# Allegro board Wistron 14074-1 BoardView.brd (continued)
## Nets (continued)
HDMI2_CLK_CON_P: C15163.2 ED2305.4 ED2305.7 EL5608.1 EL5608.2 HDMI2.10 R5610.1 R9696.1
HDMI2_CLK_CPU_N: C15164.1 CPU1.F44
HDMI2_CLK_CPU_P: C15163.1 CPU1.D44
HDMI2_DATA_CON_N0: C15166.2 ED2305.2 ED2305.9 EL5607.3 EL5607.4 HDMI2.9 R5609.2 R9691.1
HDMI2_DATA_CON_N1: C15170.2 ED2306.5 ED2306.6 EL5606.3 EL5606.4 HDMI2.6 R5608.2 R9694.1
HDMI2_DATA_CON_N2: C15172.2 ED2306.2 ED2306.9 EL5605.3 EL5605.4 HDMI2.3 R5607.2 R9697.1
HDMI2_DATA_CON_P0: C15165.2 ED2305.1 ED2305.10 EL5607.1 EL5607.2 HDMI2.7 R5609.1 R9692.1
HDMI2_DATA_CON_P1: C15167.2 ED2306.4 ED2306.7 EL5606.1 EL5606.2 HDMI2.4 R5608.1 R9693.1
HDMI2_DATA_CON_P2: C15171.2 ED2306.1 ED2306.10 EL5605.1 EL5605.2 HDMI2.1 R5607.1 R9695.1
HDMI2_DATA_CPU_N0: C15166.1 CPU1.G42
HDMI2_DATA_CPU_N1: C15170.1 CPU1.K40
HDMI2_DATA_CPU_N2: C15172.1 CPU1.G40
HDMI2_DATA_CPU_P0: C15165.1 CPU1.F42
HDMI2_DATA_CPU_P1: C15167.1 CPU1.J40
HDMI2_DATA_CPU_P2: C15171.1 CPU1.F40
HDMI2_DDCCLK_CON: EC7613.1 ED2304.3 HDMI2.15 Q6517.D R9689.2
HDMI2_DDCCLK_CPU: CPU1.T51 Q6517.S RN5402.1(A)
HDMI2_DDCCLK_G: Q6517.G RN5603.1(A) RN5603.2(A)
HDMI2_DDCDATA_CON: EC7612.1 ED2304.4 HDMI2.16 Q6518.D R9690.2
HDMI2_DDCDATA_CPU: CPU1.T52 Q6518.S RN5402.2(A)
HDMI2_DDCDATA_G: Q6518.G RN5604.1(A) RN5604.2(A)
HDMI2_HPD_CON: ED2304.1 HDMI2.19 Q6503.G R6542.1 R6557.1
HDMI2_HPD_CPU#: CPU1.U51 Q6503.D R6535.1 R6557.2
HDMI2_LS_R: Q6519.D R9691.2 R9692.2 R9693.2 R9694.2 R9695.2 R9696.2 R9697.2 R9698.2
HUB_AVDD: C4606.1 C4607.1 C4608.1 C4609.1 C4610.1 L5305.2 U4601.5 U4601.9 U4601.14
HUB_DVDD: C4601.2 C4605.1 C4611.1 L5305.1 R4602.1 R4604.1 R4608.2 R4609.1 TC4601.1 U4601.21 U4601.28 U4602.8
HUB_OC14_L: R4611.2 R4612.1 U4601.19 U4601.25
HUB_OC23_L: R4613.2 R4614.1 U4601.20 U4601.24
HUB_PGANG: R4607.1 U4601.23
HUB_PSELF: R4604.2 R4605.1 U4601.22
HUB_RESET#: C4602.1 R4602.2 R4603.1 U4601.17
HUB_RREF: R4606.1 U4601.8
HUB_SDA: R4608.1 U4601.26 U4602.5
HUB_TEST/SCL: U4601.18 U4602.6
HUB_X1: C4603.2 U4601.10 X3501.3
HUB_X2: C4604.2 U4601.11 X3501.1
HWM_REF: C2008.1 R2018.2 R2019.2 SIO1.47
ICLKICOMP: CPU1.P20 R1534.2
ICLKRCOMP: CPU1.N20 R1535.2
INT_SERIRQ_CPU: CPU1.T2 R9671.1 U2402.3
INT_SERIRQ_OE: R2474.2 R2475.1 U2402.5
JDREF: AUDIO1.40 R2213.1
KA20GATE: R2030.2 SIO1.21
KBCLK: RN5410.3(A) SIO1.39
KBDATA: RN5410.4(A) SIO1.38
KBRST_N: C2018.2 R2029.2 SIO1.20
LAD0_FWH0: CPU1.M3 DBGH1.9 SIO1.16
LAD1_FWH1: CPU1.M2 DBGH1.7 SIO1.17
LAD2_FWH2: CPU1.N3 DBGH1.3 SIO1.18
LAD3_FWH3: CPU1.N1 DBGH1.1 SIO1.19
LAN_CLKREQ_CPU#: CPU1.AM14 D2101.A R2110.1 R6519.1 R9852.1
LAN_CLKREQB: D2101.K LAN1.12 R2110.2 R2112.1
LAN_CONN_CVT: C2813.1 U3RJ1.R1
LAN_ISOLATEB: LAN1.20 R2108.1 R2109.1
LAN_LED*: L3401.2 R3422.2
LAN_LED*_EMI: L3401.1 LEDH1.12
LAN_LED_ACT: C2811.1 R2811.1 U3RJ1.L14
LAN_LED_ACT_C: LAN1.27 R2105.1
LAN_LED_ACTIVE: ED3203.1 R2105.2 R6401.2 U3RJ1.L13
LAN_LEDC0: Q3401.C R3422.1
LAN_LEDC1: Q3401.B R3420.1
LAN_LEDC1_E: Q6550.D R3418.2 R3420.2
LAN_LEDC1_E1: Q6550.S R3419.2 R6401.1 R6402.1 R6403.1
LAN_LINK_100: ED3203.3 LAN1.26 R2813.2
LAN_LINK_100_R: C2810.1 R2810.1 R2813.1 U3RJ1.L12
LAN_LINK_1000: ED3203.4 LAN1.25 R2814.2
LAN_LINK_1000_R: C2809.1 R2801.1 R2814.1 U3RJ1.L11
LAN_MDI0_DN: EC2802.1 ED2804.4 EL5337.1 EL5337.2 LAN1.2 U3RJ1.R3
LAN_MDI0_DP: EC2804.1 ED2804.3 EL5337.3 EL5337.4 LAN1.1 U3RJ1.R2
LAN_MDI1_DN: EC2806.1 ED2804.1 EL5316.1 EL5316.2 LAN1.5 U3RJ1.R5
LAN_MDI1_DP: EC2807.1 ED2804.6 EL5316.3 EL5316.4 LAN1.4 U3RJ1.R4
LAN_MDI2_DN: EC2803.1 ED2802.4 EL5317.1 EL5317.2 LAN1.7 U3RJ1.R7
LAN_MDI2_DP: EC2805.1 ED2802.3 EL5317.3 EL5317.4 LAN1.6 U3RJ1.R6
LAN_MDI3_DN: EC2801.1 ED2802.1 EL5318.1 EL5318.2 LAN1.10 U3RJ1.R9
LAN_MDI3_DP: EC2808.1 ED2802.6 EL5318.3 EL5318.4 LAN1.9 U3RJ1.R8
LAN_RSET: LAN1.31 R2106.2
LAN_WAKEB: LAN1.21 R2113.1 R9817.2
LDOVDD_IN: AUDIO1.29 C2211.2 C2212.1 L2202.1 R2203.1
LEDH1_5V: LEDH1.11 R9884.2
LFRAMEJ_FW4: CPU1.P3 DBGH1.2 SIO1.15
LINE2_JD: AUDH1.9 R2209.2
LINE2_VREFO: AUDIO1.31 D2203.3
LINE2_VREFO_D1: D2203.2 R2226.1
LINE2_VREFO_D2: D2203.1 R2229.1
LINEIN_JD: AUDR1.33 D2702.A R2206.1
LOM_WAKE_N_CPU: CPU1.P18 R1906.1
LOM_WAKE_N_CPU1: Q6549.B RN1902.3(B) RN1902.4(B)
LOM_WAKE_N_CPU2: Q6549.C R1904.1 R1906.2 R1907.2 R9859.2
LPC_CLKOUT0: CPU1.P2 R1902.2 R1903.2
LPC_CLKOUT1: CPU1.R3 R9707.2
LPC_PME_N: R2051.1 SIO1.32
M_A_A0: CPU1.BB47 DIMM1.98
M_A_A1: CPU1.BC42 DIMM1.97
M_A_A2: CPU1.BJ48 DIMM1.96
M_A_A3: CPU1.BH47 DIMM1.95
M_A_A4: CPU1.BD42 DIMM1.92
M_A_A5: CPU1.BH48 DIMM1.91
M_A_A6: CPU1.BB46 DIMM1.90
M_A_A7: CPU1.BE46 DIMM1.86
M_A_A8: CPU1.BD44 DIMM1.89
M_A_A9: CPU1.BE52 DIMM1.85
M_A_A10: CPU1.BJ45 DIMM1.107
M_A_A11: CPU1.BB49 DIMM1.84
M_A_A12: CPU1.BF48 DIMM1.83
M_A_A13: CPU1.BF44 DIMM1.119
M_A_A14: CPU1.BD47 DIMM1.80
M_A_A15: CPU1.BD49 DIMM1.78
M_A_BS0: CPU1.BH46 DIMM1.109
M_A_BS1: CPU1.AY40 DIMM1.108
M_A_BS2: CPU1.BF52 DIMM1.79
M_A_CAS#: CPU1.BG45 DIMM1.115
M_A_DIM1_CKE0: CPU1.BB44 DIMM1.73
M_A_DIM1_CKE1: CPU1.AY42 DIMM1.74
M_A_DIM1_CLK_DDR0: CPU1.BD40 DIMM1.101
M_A_DIM1_CLK_DDR1: CPU1.BD38 DIMM1.102
M_A_DIM1_CLK_DDR#0: CPU1.BF40 DIMM1.103
M_A_DIM1_CLK_DDR#1: CPU1.BF38 DIMM1.104
M_A_DIM1_CS#0: CPU1.AY38 DIMM1.114
M_A_DIM1_CS#1: CPU1.AU38 DIMM1.121
M_A_DIM1_DM0: CPU1.AP52 DIMM1.11
M_A_DIM1_DM1: CPU1.AP44 DIMM1.28
M_A_DIM1_DM2: CPU1.AT48 DIMM1.46
M_A_DIM1_DM3: CPU1.BA53 DIMM1.63
M_A_DIM1_DM4: CPU1.BG41 DIMM1.136
M_A_DIM1_DM5: CPU1.AY36 DIMM1.153
M_A_DIM1_DM6: CPU1.BD32 DIMM1.170
M_A_DIM1_DM7: CPU1.BH30 DIMM1.187
M_A_DIM1_ODT0: CPU1.AV36 DIMM1.116
M_A_DIM1_ODT1: CPU1.BA38 DIMM1.120
M_A_DQ0: CPU1.AK51 DIMM1.5
M_A_DQ1: CPU1.AL51 DIMM1.7
M_A_DQ2: CPU1.AR53 DIMM1.15
M_A_DQ3: CPU1.AP51 DIMM1.17
M_A_DQ4: CPU1.AL53 DIMM1.4
M_A_DQ5: CPU1.AK52 DIMM1.6
M_A_DQ6: CPU1.AR51 DIMM1.16
M_A_DQ7: CPU1.AT52 DIMM1.18
M_A_DQ8: CPU1.AP40 DIMM1.21
M_A_DQ9: CPU1.AV41 DIMM1.23
M_A_DQ10: CPU1.AT44 DIMM1.33
M_A_DQ11: CPU1.AT40 DIMM1.35
M_A_DQ12: CPU1.AT38 DIMM1.22
M_A_DQ13: CPU1.AP41 DIMM1.24
M_A_DQ14: CPU1.AP42 DIMM1.34
M_A_DQ15: CPU1.AV42 DIMM1.36
M_A_DQ16: CPU1.AP48 DIMM1.39
M_A_DQ17: CPU1.AT47 DIMM1.41
M_A_DQ18: CPU1.AY48 DIMM1.51
M_A_DQ19: CPU1.AV50 DIMM1.53
M_A_DQ20: CPU1.AT50 DIMM1.40
M_A_DQ21: CPU1.AP47 DIMM1.42
M_A_DQ22: CPU1.AY50 DIMM1.50
M_A_DQ23: CPU1.AV45 DIMM1.52
M_A_DQ24: CPU1.BB51 DIMM1.57
M_A_DQ25: CPU1.AV52 DIMM1.59
M_A_DQ26: CPU1.BC53 DIMM1.67
M_A_DQ27: CPU1.BD52 DIMM1.69
M_A_DQ28: CPU1.BC52 DIMM1.56
M_A_DQ29: CPU1.AW53 DIMM1.58
M_A_DQ30: CPU1.AW51 DIMM1.68
M_A_DQ31: CPU1.AV51 DIMM1.70
M_A_DQ32: CPU1.BG42 DIMM1.129
M_A_DQ33: CPU1.BG43 DIMM1.131
M_A_DQ34: CPU1.BG37 DIMM1.141
M_A_DQ35: CPU1.BJ37 DIMM1.143
M_A_DQ36: CPU1.BH42 DIMM1.130
M_A_DQ37: CPU1.BJ41 DIMM1.132
M_A_DQ38: CPU1.BH36 DIMM1.140
M_A_DQ39: CPU1.BH38 DIMM1.142
M_A_DQ40: CPU1.BC36 DIMM1.147
M_A_DQ41: CPU1.BA36 DIMM1.149
M_A_DQ42: CPU1.AU34 DIMM1.157
M_A_DQ43: CPU1.AU32 DIMM1.159
M_A_DQ44: CPU1.BF36 DIMM1.146
M_A_DQ45: CPU1.BD36 DIMM1.148
M_A_DQ46: CPU1.AV34 DIMM1.158
M_A_DQ47: CPU1.AV32 DIMM1.160
M_A_DQ48: CPU1.BF34 DIMM1.163
M_A_DQ49: CPU1.BC34 DIMM1.165
M_A_DQ50: CPU1.BF30 DIMM1.175
M_A_DQ51: CPU1.BD30 DIMM1.177
M_A_DQ52: CPU1.BD34 DIMM1.164
M_A_DQ53: CPU1.BA34 DIMM1.166
M_A_DQ54: CPU1.BA32 DIMM1.174
M_A_DQ55: CPU1.BD28 DIMM1.176
M_A_DQ56: CPU1.BG33 DIMM1.181
M_A_DQ57: CPU1.BH34 DIMM1.183
M_A_DQ58: CPU1.BJ29 DIMM1.191
M_A_DQ59: CPU1.BG29 DIMM1.193
M_A_DQ60: CPU1.BJ33 DIMM1.180
M_A_DQ61: CPU1.BG32 DIMM1.182
M_A_DQ62: CPU1.BG28 DIMM1.192
M_A_DQ63: CPU1.BH28 DIMM1.194
M_A_DQS_DN0: CPU1.AM51 DIMM1.10
M_A_DQS_DN1: CPU1.AT41 DIMM1.27
M_A_DQS_DN2: CPU1.AV48 DIMM1.45
M_A_DQS_DN3: CPU1.BA51 DIMM1.62
M_A_DQS_DN4: CPU1.BG39 DIMM1.135
M_A_DQS_DN5: CPU1.AT34 DIMM1.152
M_A_DQS_DN6: CPU1.BC32 DIMM1.169
M_A_DQS_DN7: CPU1.BG31 DIMM1.186
M_A_DQS_DP0: CPU1.AM52 DIMM1.12
M_A_DQS_DP1: CPU1.AT42 DIMM1.29
M_A_DQS_DP2: CPU1.AV47 DIMM1.47
M_A_DQS_DP3: CPU1.AY52 DIMM1.64
M_A_DQS_DP4: CPU1.BH40 DIMM1.137
M_A_DQS_DP5: CPU1.AT32 DIMM1.154
M_A_DQS_DP6: CPU1.BC30 DIMM1.171
M_A_DQS_DP7: CPU1.BH32 DIMM1.188
M_A_DRAMRST#: CPU1.BA42 R1316.2
M_A_OCAVREF: C501.1 CPU1.AT28 R509.1
M_A_OCAVREF_R: R505.2 R509.2 R513.1
M_A_ODQVREF: C504.1 CPU1.AU28 R510.1
M_A_ODQVREF_R: R506.2 R510.2 R514.1
M_A_RAS#: CPU1.BA40 DIMM1.110
M_A_RCOMP_0: CPU1.BA28 R501.1
M_A_WE#: CPU1.BH44 DIMM1.113
M_B_A0: CPU1.BB7 DIMM2.98 DIMM3.98
M_B_A1: CPU1.BC12 DIMM2.97 DIMM3.97
M_B_A2: CPU1.BJ6 DIMM2.96 DIMM3.96
M_B_A3: CPU1.BH7 DIMM2.95 DIMM3.95
M_B_A4: CPU1.BD12 DIMM2.92 DIMM3.92
M_B_A5: CPU1.BH6 DIMM2.91 DIMM3.91
M_B_A6: CPU1.BB8 DIMM2.90 DIMM3.90
M_B_A7: CPU1.BE8 DIMM2.86 DIMM3.86
M_B_A8: CPU1.BD10 DIMM2.89 DIMM3.89
M_B_A9: CPU1.BE2 DIMM2.85 DIMM3.85
M_B_A10: CPU1.BJ9 DIMM2.107 DIMM3.107
M_B_A11: CPU1.BB5 DIMM2.84 DIMM3.84
M_B_A12: CPU1.BF6 DIMM2.83 DIMM3.83
M_B_A13: CPU1.BF10 DIMM2.119 DIMM3.119
M_B_A14: CPU1.BD7 DIMM2.80 DIMM3.80
M_B_A15: CPU1.BD5 DIMM2.78 DIMM3.78
M_B_BS0: CPU1.BH8 DIMM2.109 DIMM3.109
M_B_BS1: CPU1.AY14 DIMM2.108 DIMM3.108
M_B_BS2: CPU1.BF2 DIMM2.79 DIMM3.79
M_B_CAS#: CPU1.BG9 DIMM2.115 DIMM3.115
M_B_DIM2_CKE0: CPU1.BB10 DIMM2.73 DIMM3.73
M_B_DIM2_CKE1: CPU1.AY12 DIMM2.74 DIMM3.74
M_B_DIM2_CLK_DDR0: CPU1.BD14 DIMM2.101 DIMM3.101
M_B_DIM2_CLK_DDR1: CPU1.BD16 DIMM2.102 DIMM3.102
M_B_DIM2_CLK_DDR#0: CPU1.BF14 DIMM2.103 DIMM3.103
M_B_DIM2_CLK_DDR#1: CPU1.BF16 DIMM2.104 DIMM3.104
M_B_DIM2_CS#0: CPU1.AY16 DIMM2.114 DIMM3.114
M_B_DIM2_CS#1: CPU1.AU16 DIMM2.121 DIMM3.121
M_B_DIM2_DM0: CPU1.AP2 DIMM2.11 DIMM3.11
M_B_DIM2_DM1: CPU1.AP10 DIMM2.28 DIMM3.28
M_B_DIM2_DM2: CPU1.AT6 DIMM2.46 DIMM3.46
M_B_DIM2_DM3: CPU1.BA1 DIMM2.63 DIMM3.63
M_B_DIM2_DM4: CPU1.BG13 DIMM2.136 DIMM3.136
M_B_DIM2_DM5: CPU1.AY18 DIMM2.153 DIMM3.153
M_B_DIM2_DM6: CPU1.BD22 DIMM2.170 DIMM3.170
M_B_DIM2_DM7: CPU1.BH24 DIMM2.187 DIMM3.187
M_B_DIM2_ODT0: CPU1.AV18 DIMM2.116 DIMM3.116
M_B_DIM2_ODT1: CPU1.BA16 DIMM2.120 DIMM3.120
M_B_DQ0: CPU1.AK3 DIMM2.5 DIMM3.5
M_B_DQ1: CPU1.AL1 DIMM2.7 DIMM3.7
M_B_DQ2: CPU1.AT2 DIMM2.15 DIMM3.15
M_B_DQ3: CPU1.AR3 DIMM2.17 DIMM3.17
M_B_DQ4: CPU1.AK2 DIMM2.4 DIMM3.4
M_B_DQ5: CPU1.AL3 DIMM2.6 DIMM3.6
M_B_DQ6: CPU1.AR1 DIMM2.16 DIMM3.16
M_B_DQ7: CPU1.AP3 DIMM2.18 DIMM3.18
M_B_DQ8: CPU1.AT14 DIMM2.21 DIMM3.21
M_B_DQ9: CPU1.AT16 DIMM2.23 DIMM3.23
M_B_DQ10: CPU1.AP12 DIMM2.33 DIMM3.33
M_B_DQ11: CPU1.AP14 DIMM2.24 DIMM3.24
M_B_DQ12: CPU1.AP13 DIMM2.22 DIMM3.22
M_B_DQ13: CPU1.AV13 DIMM2.35 DIMM3.35
M_B_DQ14: CPU1.AT10 DIMM2.34 DIMM3.34
M_B_DQ15: CPU1.AV12 DIMM2.36 DIMM3.36
M_B_DQ16: CPU1.AP6 DIMM2.39 DIMM3.39
M_B_DQ17: CPU1.AT7 DIMM2.41 DIMM3.41
M_B_DQ18: CPU1.AY6 DIMM2.51 DIMM3.51
M_B_DQ19: CPU1.AV4 DIMM2.53 DIMM3.53
M_B_DQ20: CPU1.AP7 DIMM2.40 DIMM3.40
M_B_DQ21: CPU1.AT4 DIMM2.42 DIMM3.42
M_B_DQ22: CPU1.AY4 DIMM2.50 DIMM3.50
M_B_DQ23: CPU1.AV9 DIMM2.52 DIMM3.52
M_B_DQ24: CPU1.BC2 DIMM2.67 DIMM3.67
M_B_DQ25: CPU1.AV2 DIMM2.58 DIMM3.58
M_B_DQ26: CPU1.AV3 DIMM2.56 DIMM3.56
M_B_DQ27: CPU1.BC1 DIMM2.68 DIMM3.68
M_B_DQ28: CPU1.AW1 DIMM2.59 DIMM3.59
M_B_DQ29: CPU1.BD2 DIMM2.69 DIMM3.69
M_B_DQ30: CPU1.AW3 DIMM2.57 DIMM3.57
M_B_DQ31: CPU1.BB3 DIMM2.70 DIMM3.70
M_B_DQ32: CPU1.BG12 DIMM2.129 DIMM3.129
M_B_DQ33: CPU1.BG11 DIMM2.131 DIMM3.131
M_B_DQ34: CPU1.BG17 DIMM2.141 DIMM3.141
M_B_DQ35: CPU1.BJ17 DIMM2.143 DIMM3.143
M_B_DQ36: CPU1.BH12 DIMM2.130 DIMM3.130
M_B_DQ37: CPU1.BJ13 DIMM2.132 DIMM3.132
M_B_DQ38: CPU1.BH18 DIMM2.140 DIMM3.140
M_B_DQ39: CPU1.BH16 DIMM2.142 DIMM3.142
M_B_DQ40: CPU1.BC18 DIMM2.147 DIMM3.147
M_B_DQ41: CPU1.BA18 DIMM2.149 DIMM3.149
M_B_DQ42: CPU1.AU20 DIMM2.157 DIMM3.157
M_B_DQ43: CPU1.AU22 DIMM2.159 DIMM3.159
M_B_DQ44: CPU1.BF18 DIMM2.146 DIMM3.146
M_B_DQ45: CPU1.BD18 DIMM2.148 DIMM3.148
M_B_DQ46: CPU1.AV20 DIMM2.158 DIMM3.158
M_B_DQ47: CPU1.AV22 DIMM2.160 DIMM3.160
M_B_DQ48: CPU1.BF20 DIMM2.163 DIMM3.163
M_B_DQ49: CPU1.BC20 DIMM2.165 DIMM3.165
M_B_DQ50: CPU1.BA22 DIMM2.175 DIMM3.175
M_B_DQ51: CPU1.BD24 DIMM2.177 DIMM3.177
M_B_DQ52: CPU1.BD20 DIMM2.164 DIMM3.164
M_B_DQ53: CPU1.BA20 DIMM2.166 DIMM3.166
M_B_DQ54: CPU1.BF24 DIMM2.174 DIMM3.174
M_B_DQ55: CPU1.BD26 DIMM2.176 DIMM3.176
M_B_DQ56: CPU1.BJ21 DIMM2.181 DIMM3.181
M_B_DQ57: CPU1.BH20 DIMM2.183 DIMM3.183
M_B_DQ58: CPU1.BG25 DIMM2.191 DIMM3.191
M_B_DQ59: CPU1.BG26 DIMM2.193 DIMM3.193
M_B_DQ60: CPU1.BG22 DIMM2.180 DIMM3.180
M_B_DQ61: CPU1.BJ25 DIMM2.194 DIMM3.194
M_B_DQ62: CPU1.BH26 DIMM2.192 DIMM3.192
M_B_DQ63: CPU1.BG21 DIMM2.182 DIMM3.182
M_B_DQS_DN0: CPU1.AM3 DIMM2.10 DIMM3.10
M_B_DQS_DN1: CPU1.AT13 DIMM2.27 DIMM3.27
M_B_DQS_DN2: CPU1.AV6 DIMM2.45 DIMM3.45
M_B_DQS_DN3: CPU1.BA3 DIMM2.62 DIMM3.62
M_B_DQS_DN4: CPU1.BG15 DIMM2.135 DIMM3.135
M_B_DQS_DN5: CPU1.AT20 DIMM2.152 DIMM3.152
M_B_DQS_DN6: CPU1.BC22 DIMM2.169 DIMM3.169
M_B_DQS_DN7: CPU1.BG23 DIMM2.186 DIMM3.186
M_B_DQS_DP0: CPU1.AM2 DIMM2.12 DIMM3.12
M_B_DQS_DP1: CPU1.AT12 DIMM2.29 DIMM3.29
M_B_DQS_DP2: CPU1.AV7 DIMM2.47 DIMM3.47
M_B_DQS_DP3: CPU1.AY2 DIMM2.64 DIMM3.64
M_B_DQS_DP4: CPU1.BH14 DIMM2.137 DIMM3.137
M_B_DQS_DP5: CPU1.AT22 DIMM2.154 DIMM3.154
M_B_DQS_DP6: CPU1.BC24 DIMM2.171 DIMM3.171
M_B_DQS_DP7: CPU1.BH22 DIMM2.188 DIMM3.188
M_B_DRAMRST#: CPU1.BA12 R1216.2
M_B_OCAVREF: C502.1 CPU1.AT26 R507.1
M_B_OCAVREF_R: R503.2 R507.2 R511.1
M_B_ODQVREF: C503.1 CPU1.AU26 R508.1
M_B_ODQVREF_R: R504.2 R508.2 R512.1
M_B_RAS#: CPU1.BA14 DIMM2.110 DIMM3.110
M_B_RCOMP_0: CPU1.BA26 R502.1
M_B_WE#: CPU1.BH10 DIMM2.113 DIMM3.113
MCSI_COMP: CPU1.P44 R9863.1
MIC1_JD: AUDR1.3 D2701.A R2208.1
MIC1_VREFO_L: AUDIO1.28 R2712.1
MIC1_VREFO_R: AUDIO1.32 R2717.1
MIC2-VREFO: AUDIO1.30 D2201.3
MIC2_JD: AUDH1.5 R2207.2
MIC2_L: AUDH1.2 C2227.2 R9794.2
MIC2_LL: Q2703.6 R2214.2 R2220.2 R9794.1
MIC2_LL*: Q2703.2 R2708.2
MIC2_R: AUDH1.4 C2228.2 R9795.2
MIC2_RR: Q2703.3 R2218.2 R2221.2 R9795.1
MIC2_RR*: Q2703.5 R2711.2
MSCLK: RN5410.1(A) SIO1.41
MSDATA: RN5410.2(A) SIO1.40
MUTE: Q2706.C R2701.1 R2704.1 R2705.1 R2708.1 R2711.1 R2714.1 R2716.1 R2718.1 R2719.1 R2723.1
MUTE_R: Q2706.B R2721.2 R2722.1
MUTE_RR: C2707.1 C2708.1 Q2707.E R2721.1
NGFF_LED_BT: NGFFE1.16 R6402.2
NGFF_LED_WLAN: NGFFE1.6 R6403.2
NGFF_SUSCLK: NGFFE1.50 R1911.2
OCP_0: PC4206.1 PR4218.1 PR4219.2 PU4202.6
OCP_1: PR4201.2 PR4204.2 PU4202.5
OCP_2: PC4206.2 PR4216.1 PR4218.2 PU4202.7 PU4203.3
OCP_3: PC4202.1 PR4202.2 PR4203.2 PR4207.1 PR4216.2 PU4202.3
OCP_4: PR4205.1 PR4206.1 PU4203.2
OCP_5: PR4202.1 PR4203.1 PR4206.2 PU4203.1
OCP_6: PR4209.2 PR4213.1 Q4202.5 Q4202.6
OCP_7: PR4208.2 PR4210.1 Q4201.G Q4202.3
OCP_8: PC4203.1 PR4222.1 PR4223.1 PR4225.1 PU4202.2
OSC_TRI: OSC1.1 R2054.1
P_1.05VLAN_OUT: L2101.1 LAN1.24 R2107.1
P_LAN_VDDREG_IN: C2102.1 C2103.1 LAN1.23 R2103.1
PCH_CLK48: OSC1.3 R9815.1
PCH_SPI_CLK: CPU1.W3 R6566.2
PCH_SPI_CLK_FLASH: EC2502.1 R6566.1 SPI1.6 U2502.6
PCH_SPI_CS0#: CPU1.V4 R6567.1
PCH_SPI_CS0#_FLASH: R6567.2 RN2502.2(A) SPI1.1 U2502.1
PCH_SPI_HOLD#: CPU1.U3 R6571.2
PCH_SPI_HOLD#_FLASH: R6571.1 RN2501.1(A) SPI1.7 U2502.7
PCH_SPI_SI: CPU1.V2 R6568.2
PCH_SPI_SI_FLASH: EC2503.1 R6568.1 SPI1.5 U2502.5
PCH_SPI_SO: CPU1.V3 R6570.1
PCH_SPI_SO_FLASH: EC2501.1 R6570.2 SPI1.2 U2502.2
PCH_SPI_WP#: CPU1.U1 R6572.1
PCH_SPI_WP#_FLASH: R6572.2 RN2502.1(A) SPI1.3 SPIH1.2 U2502.3
PCH_SPKR1: Q2711.B R2730.1
PCIE_CLKREQ2_CPU#_1D8: CPU1.AM12 R1807.1
PCIE_OBSN: CPU1.F26 R1805.1
PCIE_OBSP: CPU1.D26 R1805.2
PCIE_PRSNT1#: PCIE16.A1 R9629.1
PCIE_RST_X1: C15129.1 PCIE16.A11 R9628.1
PCIE_RX_CPU_N1: CPU1.F20 R1806.2
PCIE_RX_CPU_N2: CPU1.F22 R6108.2
PCIE_RX_CPU_N3: C15119.2 CPU1.J24
PCIE_RX_CPU_P1: CPU1.D20 R1804.2
PCIE_RX_CPU_P2: CPU1.D22 R6109.2
PCIE_RX_CPU_P3: C15118.2 CPU1.G24
PCIE_RX_GFX_N0: CPU1.J20 PCIE16.A17
PCIE_RX_GFX_N1: PCIE16.A22 R1806.1
PCIE_RX_GFX_P0: CPU1.G20 PCIE16.A16
PCIE_RX_GFX_P1: PCIE16.A21 R1804.1
PCIE_RX_LAN_N3: C15119.1 LAN1.18
PCIE_RX_LAN_P3: C15118.1 LAN1.17
PCIE_RX_WLAN_N2: NGFFE1.43 R6108.1
PCIE_RX_WLAN_P2: NGFFE1.41 R6109.1
PCIE_TX_CPU_N0: C1802.2 CPU1.B24
PCIE_TX_CPU_N1: C15112.2 CPU1.C25
PCIE_TX_CPU_N2: C15114.2 CPU1.C26
PCIE_TX_CPU_N3: C15116.2 CPU1.C27
PCIE_TX_CPU_P0: C1801.2 CPU1.C24
PCIE_TX_CPU_P1: C15113.2 CPU1.A25
PCIE_TX_CPU_P2: C15115.2 CPU1.B26
PCIE_TX_CPU_P3: C15117.2 CPU1.A27
PCIE_TX_GFX_N0: C1802.1 PCIE16.B15
PCIE_TX_GFX_N1: C15112.1 PCIE16.B20
PCIE_TX_GFX_P0: C1801.1 PCIE16.B14
PCIE_TX_GFX_P1: C15113.1 PCIE16.B19
PCIE_TX_LAN_N3: C15116.1 LAN1.14
PCIE_TX_LAN_P3: C15117.1 LAN1.13
PCIE_TX_WLAN_N2: C15114.1 NGFFE1.37
PCIE_TX_WLAN_P2: C15115.1 NGFFE1.35
PCIE_WAKE_LOM: R1905.2 R9817.1
PCIE_WAKE_LOM1: Q6549.E R1904.2 R1905.1
PCIE_WAKE_N_CPU: CPU1.N16 R1908.1
PCIE_WAKE_N_CPU1: Q6548.B RN1901.3(B) RN1901.4(B)
PCIE_WAKE_N_CPU2: Q6548.E R1901.2 R9857.1 R9858.1 R9861.1
PCIE_WAKE_N_CPU3: Q6548.C R1901.1 R1908.2 R1909.2 R9855.2
PCIE_WAKE_N_MINI: NGFFE1.55 R9857.2
PCIE_WAKE_N_X16: PCIE16.B11 R9858.2
PCIRST_LAN#: C2101.1 LAN1.19 R2101.1 R2115.1
PCU_SMB_ALERT#: CPU1.AM9 R1533.2
PLT_RST#: DBGH1.10 Q6540.3 R2115.2 R6104.1 R9628.2 R9709.1 R9818.2
PLT_RST#_CPU: CPU1.F14 R9607.2 R9788.2 R9789.2
PLT_RST#_CPU1: Q6540.2 R9789.1
PLT_RST#_CPU2: Q6540.5 Q6540.6 R9790.1
PLT_WLAN_RST#: C6105.1 NGFFE1.52 R6104.2 R6105.2
PLTRST_SIO_N: C2015.2 R2036.2 R9709.2 SIO1.13
PM_CLKRUN#: CPU1.T3 R9675.1
PM_EXTTS#0: DIMM1.198 R1301.1
PM_EXTTS#1: DIMM2.198 DIMM3.198 R1201.1
PM_PWRBTN#_CPU: CPU1.M16 Q6539.C R1910.1 R1920.2
PM_PWRBTN#_CPU1: Q6539.B RN1903.3(B) RN1903.4(B)
PM_PWRBTN#_XDP: R9605.2 XDP1.41
PM_SLP_S0IX: PR9763.1 Q6541.3 RN5408.2(A)
PM_SLP_S0IX_CPU: CPU1.A13 R9792.2 R9793.2
PM_SLP_S0IX_CPU1: Q6541.2 R9793.1
PM_SLP_S0IX_CPU2: Q6541.5 Q6541.6 RN5408.1(A)
PM_SLP_S3#_CPU: CPU1.B14 R9732.2 R9733.2
PM_SLP_S4#_CPU: CPU1.C12 R9734.2 R9735.2
PMC_BATLOW#: CPU1.C14 R9674.1
PMC_RSTBTN#: C3404.1 C3405.1 C3406.1 C7542.1 CPU1.AF2 D3401.K R1915.1 R3406.1 R9613.2
PMU_SUSCLK_CPU: CPU1.C15 R1911.1
POL1_SDA: R9654.1 R9655.2 U6506.22 U6519.5
POL2_SCL: R9656.1 R9657.2 U6506.23 U6519.6
PORT80_SW: DBGH1.4 R3202.2
PWR_0D675V_EN_S3: PC5037.1 PR5232.2 PR5234.2 PR9763.2 PU5004.7
PWR_1D5V_EN: PC5222.1 PR5110.1 PU5102.3 R9736.2 R9737.2
PWR_1D5V_VIN: PC5110.1 PR5108.2 PU5102.1
PWR_1D8V_A: PC5107.1 PC5108.1 PC5109.1 PL5101.2 PR5101.1 PR5222.1 PR5223.1 PR5224.1 PR5225.1 PT5102.1
PWR_1D8V_BOOT: PR5106.2 PU5101.10
PWR_1D8V_BOOT_1: PC5105.2 PR5106.1
PWR_1D8V_CS: PR5107.1 PU5101.2
PWR_1D8V_EN: PC5219.1 PU5101.3 R5004.2 R9728.2
PWR_1D8V_FB: PC5107.2 PR5101.2 PR5102.1 PU5101.4
PWR_1D8V_HG: PR5117.2 PU5101.9
PWR_1D8V_HG_1: PQ5101.4 PR5103.2 PR5117.1
PWR_1D8V_LG: PQ5102.4 PU5101.6
PWR_1D8V_LX: PC5105.1 PL5101.1 PQ5101.1 PQ5101.2 PQ5101.3 PQ5102.5 PQ5102.6 PQ5102.7 PQ5102.8 PR5103.1 PR5105.1 PU5101.8
PWR_1D8V_RF: PR5116.1 PU5101.5
PWR_1D8V_SN: PC5106.1 PR5105.2
PWR_1D8V_VCC: PC5104.1 PR5104.2 PU5101.7
PWR_1D8V_VIN: PC5101.1 PC5102.1 PL5006.1 PL5102.1 PQ5101.5 PQ5101.6 PQ5101.7 PQ5101.8 PT5101.1
PWR_1D24V_A: PC5215.1 PC5216.1 PC5217.1 PC5218.1 PR5213.1 PR5214.1 PU5202.3 PU5202.4
PWR_1D24V_CNTL: PC5213.1 PR5209.1 PU5202.6
PWR_1D24V_EN: PC5221.1 PU5202.8 R9731.2
PWR_1D24V_FB: PC5215.2 PR5211.1 PR5214.2 PU5202.2
PWR_1D24V_VIN: PC5212.1 PC5214.1 PR5210.1 PU5202.5 PU5202.9
PWR_1D35V_EN_S5: PC5036.1 PR5233.2 PU5004.8
PWR_1P05V_BOOT: PR4714.2 PU4701.10
PWR_1P05V_BOOT_1: PC4703.1 PR4714.1
PWR_1P05V_CS: PR4711.1 PU4701.2
PWR_1P05V_EN: C15175.1 PU4701.3 Q6528.6 RN5411.2(A)
PWR_1P05V_EN1: C15174.1 Q6528.5 RN5411.1(A)
PWR_1P05V_EN2: Q6528.2 Q6528.3 R9725.2
PWR_1P05V_FB: PC4705.2 PR4717.2 PR4718.1 PU4701.4
PWR_1P05V_HG: PR4716.2 PU4701.9
PWR_1P05V_HG_1: PQ4701.4 PR4715.2 PR4716.1
PWR_1P05V_LG: PQ4702.4 PU4701.6
PWR_1P05V_LX: PC4703.2 PL4701.1 PQ4701.1 PQ4701.2 PQ4701.3 PQ4702.5 PQ4702.6 PQ4702.7 PQ4702.8 PR4713.1 PR4715.1 PU4701.8
PWR_1P05V_RF: PR4702.1 PU4701.5
PWR_1P05V_SN: PC4704.1 PR4713.2
PWR_1P05V_VCC: PC4702.1 PR4701.2 PU4701.7
PWR_1P05V_VIN: PC4706.1 PC4711.1 PL4702.1 PL4703.1 PL5103.1 PQ4701.5 PQ4701.6 PQ4701.7 PQ4701.8 PT4702.1
PWR_1P15V_CNTL: PC4802.1 PR4802.1 PU4801.6
PWR_1P15V_EN: PC5220.1 PU4801.8 R9729.2 R9730.2
PWR_1P15V_FB: PC4805.2 PR4803.1 PR4806.2 PU4801.2
PWR_1P15V_VIN: PC4803.1 PC4804.1 PR4801.1 PU4801.5 PU4801.9
PWR_12V_BOOT: PR5014.2 PU5001.1
PWR_12V_BOOT1: PC5004.1 PR5010.2 PR5014.1
PWR_12V_BT1: PD5001.K PR5010.1
PWR_12V_COMP: PC5005.2 PQ5005.3 PR5003.1 PU5001.7
PWR_12V_CP1: PC5008.2 PR5003.2
PWR_12V_ENABLE1: C5001.1 PQ5005.5 PQ5005.6 R5001.1 R5002.1
PWR_12V_ENABLE2: PQ5005.2 R5003.2
PWR_12V_FB: PC5002.1 PC5005.1 PC5008.1 PR5005.2 PR5006.1 PU5001.8
PWR_12V_FB1: PC5002.2 PR5004.2
PWR_12V_LG: PQ5004.4 PR5002.1 PU5001.4
PWR_12V_LX: PC5004.2 PL5005.1 PQ5003.1 PQ5003.2 PQ5003.3 PQ5004.5 PQ5004.6 PQ5004.7 PQ5004.8 PR5011.1 PR5016.2 PU5001.2
PWR_12V_SNB: PC5001.1 PR5011.2
PWR_12V_UG: PR5001.1 PU5001.3
PWR_12V_UG1: PQ5003.4 PR5001.2 PR5016.1
PWR_12V_VCC: PC5009.1 PR5013.2 PU5001.6
PWR_12V_VOS: PC5006.1 PR5017.1 PR5018.1 PU5001.9
PWR_AD+_2: PC4205.2 PR4214.1 PR4215.1 PU4201.4
PWR_BTN_N: C3411.2 R2011.2 R2026.1 R2045.1 R3409.2 R3410.2
PWR_BTNJ_C: C3410.1 LEDH1.6 R3410.1
PWR_DDR_BT: PR5030.2 PU5004.18
PWR_DDR_BT1: PC5040.2 PR5030.1
PWR_DDR_CS: PR5023.2 PU5004.13
PWR_DDR_FB: PC5032.2 PR5012.1 PR5041.2 PU5004.6
PWR_DDR_LDOIN: PC5028.1 PR5034.1 PU5004.19
PWR_DDR_LG: PQ5002.4 PU5004.15
PWR_DDR_LX: PC5040.1 PL5001.1 PQ5001.1 PQ5001.2 PQ5001.3 PQ5002.5 PQ5002.6 PQ5002.7 PQ5002.8 PR5029.1 PU5004.16
PWR_DDR_SNB: PC5041.1 PR5029.2
PWR_DDR_TON: PR5031.2 PU5004.9
PWR_DDR_UG: PR5037.2 PU5004.17
PWR_DDR_UG1: PQ5001.4 PR5037.1
PWR_DDR_VDD: PC5034.2 PR5023.1 PR5024.2 PU5004.11
PWR_DDR_VDDQ: PR5035.1 PU5004.5
PWR_DDR_VTT: PC5031.1 PC5033.1 PR5027.2 PU5004.2 PU5004.20
PWR_DDR_VTTREF: PC5030.1 PU5004.4
PWR_LEDC1: Q3404.B R3415.1
PWR_LEDC1_D: Q3403.D R3413.2 R3415.2
PWR_LEDJ_C: C3403.1 L5313.2 LEDH1.2
PWR_LEDJ_L: L5313.1 R3416.2
PWR_LEDJ_P: Q3404.C R3416.1
PWR_RT8243_3VFB: PC4911.2 PG4902.1 PR4914.1
PWR_RT8243_BT1: PR4903.1 PU4902.19
PWR_RT8243_BT1R: PC4908.1 PR4903.2
PWR_RT8243_BT2: PR4926.2 PU4902.7
PWR_RT8243_BT2R: PC4927.2 PR4926.1
PWR_RT8243_BYP1: PC4912.1 PC4913.1 PG4903.2 PR4920.2 PU4902.20
PWR_RT8243_EMN: PR4917.2 PR4919.1 PU4902.13
PWR_RT8243_ENLDO: PR4925.2 PU4902.12
PWR_RT8243_ENTRIP1: PC4917.1 PR4924.1 PU4902.2
PWR_RT8243_ENTRIP2: PC4918.1 PR4923.1 PU4902.4
PWR_RT8243_FB1: PC4913.2 PR4920.1 PR4921.1 PU4902.1
PWR_RT8243_FB2: PC4911.1 PR4914.2 PR4916.1 PU4902.5
PWR_RT8243_LDO3: PC4914.1 PG4904.1 PU4902.15
PWR_RT8243_LDO5: PC4926.1 PG4901.1 PU4902.14
PWR_RT8243_LG1: PQ4902.4 PU4902.16
PWR_RT8243_LG2: PQ4904.4 PU4902.10
PWR_RT8243_LX1: PC4908.2 PL4904.1 PQ4901.1 PQ4901.2 PQ4901.3 PQ4902.5 PQ4902.6 PQ4902.7 PQ4902.8 PR4912.1 PU4902.17
PWR_RT8243_LX2: PC4927.1 PL4903.2 PQ4903.1 PQ4903.2 PQ4903.3 PQ4904.5 PQ4904.6 PQ4904.7 PQ4904.8 PR4911.1 PU4902.9
PWR_RT8243_PG: PR4922.2 PU4902.6
PWR_RT8243_SNB1: PC4915.1 PR4912.2
PWR_RT8243_SNB2: PC4916.1 PR4911.2
PWR_RT8243_TON: PR4918.1 PU4902.3
PWR_RT8243_UG1: PR4905.2 PU4902.18
PWR_RT8243_UG1R: PQ4901.4 PR4905.1
PWR_RT8243_UG2: PR4904.1 PU4902.8
PWR_RT8243_UG2R: PQ4903.4 PR4904.2
PWR_VCC0_BT: PR4424.2 PU4401.8
PWR_VCC0_BTR: PC4421.2 PR4424.1
PWR_VCC0_COMP: PC4412.1 PC4413.1 PU4401.23
PWR_VCC0_COMP1: PC4411.2 PR4404.1
PWR_VCC0_COMP2: PC4413.2 PR4407.1
PWR_VCC0_CSCOMP: PC4419.2 PC4420.2 PN4402.1 PR4418.1 PR4419.2 PU4401.19
PWR_VCC0_CSMP1: PN4402.2 PR4419.1 PR4420.2
PWR_VCC0_CSN: PG4402.2 PR4416.1
PWR_VCC0_CSP: PG4401.2 PR4417.1
PWR_VCC0_CSREF: PC4418.1 PR4416.2 PU4401.17
PWR_VCC0_CSSUM: PC4419.1 PC4420.1 PR4417.2 PR4420.1 PU4401.18
PWR_VCC0_DIFFOUT: PR4404.2 PR4405.2 PU4401.25
PWR_VCC0_FB: PC4411.1 PC4412.2 PR4405.1 PR4406.1 PR4407.2 PU4401.24
PWR_VCC0_HG: PR4423.2 PU4401.9
PWR_VCC0_HGR: PQ4401.4 PR4422.1 PR4423.1
PWR_VCC0_ILIM: PR4418.2 PU4401.21
PWR_VCC0_IMAX: PR4432.1 PU4401.16
PWR_VCC0_IOUT: PC4417.1 PR4415.1 PU4401.20
PWR_VCC0_LG: PQ4402.4 PU4401.12
PWR_VCC0_PVCC: PC4426.1 PR4428.2 PU4401.15
PWR_VCC0_ROSC: PR4433.1 PU4401.22
PWR_VCC0_SN: PC4429.1 PR4421.2
PWR_VCC0_SW: PC4421.1 PG4401.1 PL4401.1 PQ4401.1 PQ4401.2 PQ4401.3 PQ4402.5 PQ4402.6 PQ4402.7 PQ4402.8 PR4421.1 PR4422.2 PU4401.10
PWR_VCC0_TSEN: PC4416.1 PR4413.1 PU4401.13
PWR_VCC0_TSEN1: PN4401.1 PR4413.2 PR4414.1
PWR_VCC0_VBOOT/ADDR: PR4431.1 PU4401.14
PWR_VCC0_VCC: PC4428.1 PR4430.2 PU4401.28
PWR_VCC0_VIN: PC4423.1 PC4424.1 PC4431.1 PL4402.2 PL4403.2 PQ4401.5 PQ4401.6 PQ4401.7 PQ4401.8 PT4491.1
PWR_VCC0_VRMP: PC4427.1 PR4429.2 PR4434.2 PU4401.7
PWR_VCC0_VSN: PC4415.1 PR4411.1 PU4401.26
PWR_VCC0_VSP: PC4414.2 PR4410.2 PU4401.27
PWR_VCORE_ENABLE: D3404.3 PC4410.1 PU4401.1 R9740.2 R9741.1
PWR_VGG_BT: PR4524.2 PU4501.8
PWR_VGG_BTR: PC4521.2 PR4524.1
PWR_VGG_COMP: PC4512.1 PC4513.1 PU4501.23
PWR_VGG_COMP1: PC4511.2 PR4504.1
PWR_VGG_COMP2: PC4513.2 PR4507.1
PWR_VGG_CSCOMP: PC4519.2 PC4520.2 PN4502.1 PR4518.1 PR4519.2 PU4501.19
PWR_VGG_CSMP1: PN4502.2 PR4519.1 PR4520.2
PWR_VGG_CSN: PG4502.2 PR4516.1
PWR_VGG_CSP: PG4501.2 PR4517.1
PWR_VGG_CSREF: PC4518.1 PR4516.2 PU4501.17
PWR_VGG_CSSUM: PC4519.1 PC4520.1 PR4517.2 PR4520.1 PU4501.18
PWR_VGG_DIFFOUT: PR4504.2 PR4505.2 PU4501.25
PWR_VGG_ENABLE: D3402.3 D3403.3 PC4510.1 PU4501.1 R4503.1 R9739.2
PWR_VGG_FB: PC4511.1 PC4512.2 PR4505.1 PR4506.1 PR4507.2 PU4501.24
PWR_VGG_HG: PR4523.2 PU4501.9
PWR_VGG_HGR: PQ4501.4 PR4522.1 PR4523.1
PWR_VGG_ILIM: PR4518.2 PU4501.21
PWR_VGG_IMAX: PR4532.1 PU4501.16
PWR_VGG_IOUT: PC4517.1 PR4515.1 PU4501.20
PWR_VGG_LG: PQ4502.4 PU4501.12
PWR_VGG_PVCC: PC4526.1 PR4528.2 PU4501.15
PWR_VGG_ROSC: PR4533.1 PU4501.22
PWR_VGG_SN: PC4529.1 PR4521.2
PWR_VGG_SW: PC4521.1 PG4501.1 PL4501.1 PQ4501.1 PQ4501.2 PQ4501.3 PQ4502.5 PQ4502.6 PQ4502.7 PQ4502.8 PR4521.1 PR4522.2 PU4501.10
PWR_VGG_TSEN: PC4516.1 PR4513.1 PU4501.13
PWR_VGG_TSEN1: PN4501.1 PR4513.2 PR4514.1
PWR_VGG_VBOOT/ADDR: PR4531.1 PU4501.14
PWR_VGG_VCC: PC4528.1 PR4530.2 PU4501.28
PWR_VGG_VIN: PC4523.1 PC4524.1 PC4531.1 PL4502.2 PL4601.2 PQ4501.5 PQ4501.6 PQ4501.7 PQ4501.8 PT4591.1
PWR_VGG_VRMP: PC4527.1 PR4529.2 PR4601.2 PU4501.7
PWR_VGG_VSN: PC4515.1 PR4511.1 PU4501.26
PWR_VGG_VSP: PC4514.2 PR4510.2 PU4501.27
PWRGD3V_150MS: C2001.1 Q4202.2 R2043.1 R9762.1 SIO1.36
PWRGD_PS_L: C7924.1 Q4001.2 R4003.2 R4004.1
PWRGD_PS_L1: Q4001.5 Q4001.6 R4005.2
RCOMP_LPC_HVT: CPU1.T4 R1935.2
RSMRST#_CPU: C15178.2 CPU1.F18 R1912.1 R9787.1
RSMRST#_R: R2007.1 SIO1.43
RSMRST_N: C2010.1 R2004.2 R2007.2 R9604.1 R9787.2
RSVD#: CPU1.B46 R1603.1
RTC_AUX_S5: C1132.1 C15110.1 C15111.1 CPU1.B6 CPU1.C5 D1501.3 R1918.1 R1919.1 R2015.2
RTC_INTRUDER: CPU1.G18 R1945.1
RTC_RST#: C7537.1 CMOS1.2 CPU1.J16 G1902.2 R1918.2
RTC_RST#_DOWN: CMOS1.3 R6573.1
RTC_X1: C7540.1 CPU1.M18 R1917.1 X3502.4
RTC_X2: C7538.1 CPU1.K18 R1917.2 X3502.1
RTD2168_AVCC12: C15151.2 C15152.2 C15153.2 U6506.19 U6506.25
RTD2168_AVCC33: C15147.1 C15154.2 L5311.2 U6506.24
RTD2168_DAC33: C15148.1 C15155.2 C15156.2 L5312.2 U6506.9
RTD2168_LDO_EN: R9648.2 R9649.1 U6506.21
RTD2168_RRX: R9647.2 U6506.28
RTD2168_SMBUS_ON: Q6542.2 Q6542.5 Q6543.2 Q6543.5 Q6553.C R9813.1 R9814.1 R9866.1
RTD2168_SMBUS_ON_1: Q6553.B RN1503.3(B) RN1503.4(B)
SA0_A_0: DIMM1.197 R1303.2 R1309.1
SA0_B_0: DIMM2.197 DIMM3.197 R1205.2 R1209.1
SA1_A_0: DIMM1.201 R1302.2 R1308.1
SA1_B_0: DIMM2.201 DIMM3.201 R1204.2 R1208.1
SATA_LED#: CPU1.AH3 Q6504.E R6404.1 R6565.1
SATA_LED_OUT: C3416.1 LEDH1.3 Q6504.C R6564.1
SATA_LED_OUT1: Q6504.B RN6401.3(B) RN6401.4(B)
SATA_OBSN: CPU1.M30 R1803.1
SATA_OBSP: CPU1.N30 R1803.2
SATA_RX_CON_N0: C1418.2 SATA0.3
SATA_RX_CON_N1: C1421.2 SATA1.3
SATA_RX_CON_P0: C1417.2 SATA0.2
SATA_RX_CON_P1: C1420.2 SATA1.2
SATA_RX_CPU_N0: C1418.1 CPU1.M28 EL5334.2 EL5334.4
SATA_RX_CPU_N1: C1421.1 CPU1.K28 EL5336.2 EL5336.4
SATA_RX_CPU_P0: C1417.1 CPU1.N28 EL5334.1 EL5334.3
SATA_RX_CPU_P1: C1420.1 CPU1.J28 EL5336.1 EL5336.3
SATA_TX_CON_N0: C1413.2 SATA0.5
SATA_TX_CON_N1: C1419.2 SATA1.5
SATA_TX_CON_P0: C1412.2 SATA0.6
SATA_TX_CON_P1: C1422.2 SATA1.6
SATA_TX_CPU_N0: C1413.1 CPU1.B30 EL5333.2 EL5333.4
SATA_TX_CPU_N1: C1419.1 CPU1.A29 EL5335.2 EL5335.4
SATA_TX_CPU_P0: C1412.1 CPU1.C31 EL5333.1 EL5333.3
SATA_TX_CPU_P1: C1422.1 CPU1.C29 EL5335.1 EL5335.3
SDMMC1_RCOMP: CPU1.P13 R804.1
SDMMC3_RCOMP: CPU1.P12 R809.1
SEC_GPIO_SUS8: CPU1.AF51 R1508.2 R1523.1
SEC_GPIO_SUS9: CPU1.AF52 R1510.2 R1525.1
SEC_GPIO_SUS10: CPU1.AE51 R1511.2 R1526.1
SENSE_A: AUDIO1.13 R2205.2 R2206.2 R2208.2
SENSE_B: AUDIO1.34 R2204.1 R2207.1 R2209.1
SERIRQ_N: R2022.1 SIO1.14 U2402.4
SIO_CLKIN: EC7615.1 R9707.1 R9816.1
SIO_EUP_EN: Q3514.G Q4304.G R3527.2 R9708.1
SIO_GND: C2002.2 C2006.2 C2009.2 C2011.2 C2016.2 C2019.2 C2020.2 G1.1 R2005.2 R2010.2 R2014.2 R2020.2 R2021.2 SIO1.44
SIO_GP31: GPIO1.1 R2028.1 SIO1.64
SIO_GP31_R: GPIO1.2 R2034.1
SIO_GP32: GPIO2.1 R2027.1 SIO1.63
SIO_GP32_R: GPIO2.2 R2033.1
SIO_LAN_RST: R2037.2 R2101.2 SIO1.10
SIO_PB_IN: C2014.1 R2011.1 SIO1.33
SIO_PCICLK: EC7616.1 R1902.1 SIO1.22
SIO_PSON_N: Q2001.G Q5401.G R3404.1 R5001.2 SIO1.34
SIO_PSON_N_1: Q2001.D R2056.2
SIO_PWNBTN_N: Q6539.E R1910.2 R2026.2 R2041.1 R9605.1 SIO1.31
SIO_PWRGD: R2025.1 SIO1.9
SIO_PWRLED_N: Q3403.S R3414.2 SIO1.37
SIO_VCORE: C2013.1 SIO1.12
SIO_VIN0: C2002.1 R2001.1 SIO1.52
SIO_VIN1: C2006.1 R2002.1 SIO1.51
SIO_VIN2: C2009.1 R2003.1 R2005.1 SIO1.50
SIO_VIN3: C2011.1 R2008.1 R2010.1 SIO1.49
SIO_VIN4: C2016.1 R2013.1 R2014.1 SIO1.48
SLP_S3#_LS1: Q6530.2 R9732.1
SLP_S3#_LS2: Q6530.5 Q6530.6 Q6551.B RN5409.1(A)
SLP_S3_N: D3402.1 Q6530.3 Q6544.G R9730.1 RN5409.2(A) U2901.5 U2903.5 U6510.5 U6511.5
SLP_S3_N_B: PR5234.1 Q4101.5 Q6551.C R3407.2 R3526.2 R5003.1 R9736.1 R9872.2 SIO1.30
SLP_S4#_LS1: Q6531.2 R9735.1
SLP_S4#_LS2: Q6531.5 Q6531.6 RN5407.1(A)
SLP_S4_N: PR5233.1 Q6531.3 R9772.1 R9829.1 R9831.1 R9836.1 R9839.1 RN5407.2(A) SIO1.35
SMB_CLK: DIMM1.202 DIMM2.202 DIMM3.202 PCIE16.B5 Q6510.S Q6542.1 R9664.2 R9809.1 RN6102.1(A) RN9901.2(A)
SMB_CLK_2168: Q6542.6 Q6543.6 R9812.1
SMB_CLK_CPU: CPU1.AM6 Q6509.S R9660.2
SMB_CLK_M: Q6509.D Q6510.D R1226.2
SMB_CLK_MINI: NGFFE1.60 RN6102.4(B)
SMB_CLK_XDP: RN9901.3(B) XDP1.53
SMB_DATA: DIMM1.200 DIMM2.200 DIMM3.200 PCIE16.B6 Q6512.S Q6542.4 R9663.2 R9810.1 RN6102.2(A) RN9901.1(A)
SMB_DATA_2168: Q6542.3 Q6543.3 R9811.1
SMB_DATA_CPU: CPU1.AM7 Q6511.S R9662.2
SMB_DATA_M: Q6511.D Q6512.D R9661.2
SMB_DATA_MINI: NGFFE1.58 RN6102.3(B)
SMB_DATA_XDP: RN9901.4(B) XDP1.51
SOC_EXTSMI_N: CPU1.AG53 Q6552.C R1509.2 R1524.1 R1542.2
SOC_RUNTIME_SCI#: CPU1.AG51 R1507.2 R1522.1 R9608.1
SOC_WAKE_SCI_N: CPU1.AD51 R1501.2 R1516.1
SP1_DCD_N: R2024.1 R2057.2 SIO1.62
SP1_DTR_N: R2032.2 SIO1.61
SP1_RTS_N: R2035.2 SIO1.57
SP1_RXD: R6803.1 R9882.2 SIO1.60
SP1_TXD: R2031.2 R6804.1 SIO1.59
SPI_WP_N_PU: RN2501.2(A) SPIH1.3
SRTC_RST#: C7539.1 CPU1.D18 G1901.2 R1919.2
SUS_PWRDN_ACK_CPU: CPU1.AE3 R1933.1
SVID_ALERT#_CPU: CPU1.AD40 R9751.1 R9753.1 R9754.1
SVID_ALERT#_VCORE: PR4427.2 PU4401.4 R9753.2
SVID_ALERT#_VGG: PR4527.2 PU4501.4 R9754.2
SVID_CLK_CPU: CPU1.AD42 R9744.1 R9745.1 R9746.1 R9873.1
SVID_CLK_VCORE: PR4426.2 PU4401.5 R9745.2
SVID_CLK_VGG: PR4526.2 PU4501.5 R9746.2
SVID_DATA_CPU: CPU1.AD41 R9875.1 R9876.1
SVID_DATA_VCORE: PR9758.1 PU4401.3 R9756.2
SVID_DATA_VCORE_R: R9755.1 R9756.1 R9875.2
SVID_DATA_VGG: PR9759.1 PU4501.3 R9757.2
SVID_DATA_VGG_R: R9757.1 R9874.1 R9876.2
SYS_FAN_3P_G: Q2503.C R2508.2 R2511.1 R2512.1
SYS_FAN_3P_POWER: FANC1.2 FANC2.2 Q2501.C Q2502.C R2501.2 R2509.2 TC2501.1
SYS_FAN_FB: Q2503.E R2501.1 R2516.1
SYS_FAN_M: Q2501.B R2511.2
SYS_FAN_M1: Q2502.B R2512.2
SYS_FAN_TACH1_1: FANC1.3 FANC2.3 R2517.2 R2518.1
SYS_FAN_TACH1_2: R2518.2 R2519.1 R2520.1
SYS_PWRGD: Q6533.3 R9764.1 R9765.1 R9767.2
SYS_PWRGD1: Q6533.2 R9762.2
SYS_PWRGD2: Q6532.B R9761.2
SYS_PWRGD3: Q6532.C Q6533.1
SYS_PWRGD4: Q6533.5 Q6533.6 R9766.2
SYS_THERMDA: C2020.1 R2019.1 R2021.1 SIO1.45
SYSTEM_FAN_PWM1_1: D2502.A FANC2.4 R2510.2 R2513.2 R2514.2
SYSTEM_FAN_PWM1_2: C2503.1 R2514.1 R2515.1
SYSTEM_FAN_PWM1_3: Q2503.B R2515.2
THERMAL_SHUT#: Q6552.E R1542.1 R2047.1 SIO1.8
THERMAL_SHUT#_1: Q6552.B RN1501.3(B) RN1501.4(B)
TP_CLK_ITP_100M_CK505_DN: TP9602.1 XDP1.42
TP_CLK_ITP_100M_CK505_DP: TP9601.1 XDP1.40
TXE_1: R1540.2 TXE1.1
TXE_2: R1541.1 TXE1.3
UART0_RXD: CPU1.AD12 R6801.1
UART0_TXD: CPU1.AD10 R6802.1
UART_RXD: R6801.2 R6803.2 UART1.1
UART_TXD: R6802.2 R6804.2 UART1.2
USB3_OBSN: CPU1.F34 R6563.1
USB3_OBSP: CPU1.D34 R6563.2
USB30_RX_CPU_N0: CPU1.D28 EL5330.1
USB30_RX_CPU_N1: CPU1.D30 EL5332.2
USB30_RX_CPU_N2: CPU1.J32 EL5324.2
USB30_RX_CPU_N3: CPU1.J34 EL5326.1
USB30_RX_CPU_P0: CPU1.F28 EL5330.2
USB30_RX_CPU_P1: CPU1.F30 EL5332.1
USB30_RX_CPU_P2: CPU1.G32 EL5324.1
USB30_RX_CPU_P3: CPU1.G34 EL5326.2
USB30_RX_FRONT_N0: ED6513.4 ED6513.7 EL5330.3 USB3F1.2
USB30_RX_FRONT_N1: ED6514.5 ED6514.6 EL5332.4 USB3F1.18
USB30_RX_FRONT_P0: ED6513.5 ED6513.6 EL5330.4 USB3F1.3
USB30_RX_FRONT_P1: ED6514.4 ED6514.7 EL5332.3 USB3F1.17
USB30_RX_REAR_N2: ED2307.2 ED2307.9 EL5324.4 U3RJ1.14
USB30_RX_REAR_N3: ED2307.4 ED2307.7 EL5326.3 U3RJ1.5
USB30_RX_REAR_P2: ED2307.1 ED2307.10 EL5324.3 U3RJ1.15
USB30_RX_REAR_P3: ED2307.5 ED2307.6 EL5326.4 U3RJ1.6
USB30_TX_CPU_N0: C15124.1 CPU1.C32
USB30_TX_CPU_N1: C15127.1 CPU1.C33
USB30_TX_CPU_N2: C15120.1 CPU1.B34
USB30_TX_CPU_N3: C15122.1 CPU1.A35
USB30_TX_CPU_P0: C15125.1 CPU1.B32
USB30_TX_CPU_P1: C15126.1 CPU1.A33
USB30_TX_CPU_P2: C15121.1 CPU1.C34
USB30_TX_CPU_P3: C15123.1 CPU1.C35
USB30_TX_FRONT_N0: ED6513.2 ED6513.9 EL5328.4 USB3F1.5
USB30_TX_FRONT_N0_C: C15124.2 EL5328.2
USB30_TX_FRONT_N1: ED6514.2 ED6514.9 EL5331.4 USB3F1.15
USB30_TX_FRONT_N1_C: C15127.2 EL5331.2
USB30_TX_FRONT_P0: ED6513.1 ED6513.10 EL5328.3 USB3F1.6
USB30_TX_FRONT_P0_C: C15125.2 EL5328.1
USB30_TX_FRONT_P1: ED6514.1 ED6514.10 EL5331.3 USB3F1.14
USB30_TX_FRONT_P1_C: C15126.2 EL5331.1
USB30_TX_REAR_N2: ED2308.5 ED2308.6 EL5314.4 U3RJ1.17
USB30_TX_REAR_N2_C: C15120.2 EL5314.2
USB30_TX_REAR_N3: ED2308.2 ED2308.9 EL5325.4 U3RJ1.8
USB30_TX_REAR_N3_C: C15122.2 EL5325.2
USB30_TX_REAR_P2: ED2308.4 ED2308.7 EL5314.3 U3RJ1.18
USB30_TX_REAR_P2_C: C15121.2 EL5314.1
USB30_TX_REAR_P3: ED2308.1 ED2308.10 EL5325.3 U3RJ1.9
USB30_TX_REAR_P3_C: C15123.2 EL5325.1
USB30_VCCA_0: C2903.1 ED2801.5 R1601.1 R2903.1 R3704.2 TC4602.1 U3RJ1.1 U3RJ1.10 U3801.1 U6510.7 U6510.8
USB30_VCCA_0_EN: C15184.1 R9836.2 R9837.2 U3801.4 U6510.4
USB30_VCCA_1: ED6521.5 R3703.2 TC4606.1 U3702.1 U6511.7 U6511.8 USB2R1.1 USB2R1.5
USB30_VCCA_1_EN: C15185.1 R9838.2 R9839.2 U3702.4 U6511.4
USB_CPU_PN0: CPU1.B42 EL5327.1
USB_CPU_PN1: CPU1.B44 EL5329.1
USB_CPU_PN2: CPU1.A41 EL5322.4
USB_CPU_PN3: CPU1.A45 EL5323.4
USB_CPU_PN4: CPU1.C40 RN3601.2(A)
USB_CPU_PN4_R: RN3601.3(B) RN5404.4(B) U4601.1
USB_CPU_PP0: CPU1.C42 EL5327.4
USB_CPU_PP1: CPU1.C43 EL5329.4
USB_CPU_PP2: CPU1.C41 EL5322.1
USB_CPU_PP3: CPU1.C45 EL5323.1
USB_CPU_PP4: CPU1.B40 RN3601.1(A)
USB_CPU_PP4_R: RN3601.4(B) RN5404.3(B) U4601.2
USB_CR_PN2: ED2907.1 EL5321.2 USB2F1.4
USB_CR_PP2: ED2907.6 EL5321.3 USB2F1.3
USB_FRONT_PN0: ED6512.6 EL5327.2 USB2F2.8 USB3F1.8
USB_FRONT_PN1: ED6512.3 EL5329.2 USB2F2.7 USB3F1.12
USB_FRONT_PP0: ED6512.1 EL5327.3 USB2F2.6 USB3F1.9
USB_FRONT_PP1: ED6512.4 EL5329.3 USB2F2.5 USB3F1.11
USB_HSIC_RCOMP: CPU1.N38 R6560.1
USB_HUB_CON_PN1: ED6521.6 EL5609.3 USB2R1.6
USB_HUB_CON_PN4: ED6521.4 EL5610.3 USB2R1.2
USB_HUB_CON_PP1: ED6521.1 EL5609.2 USB2R1.7
USB_HUB_CON_PP4: ED6521.3 EL5610.2 USB2R1.3
USB_HUB_PN1: EL5609.4 U4601.3
USB_HUB_PN2: EL5321.1 RN5404.1(A) U4601.6
USB_HUB_PN3: NGFFE1.5 U4601.12
USB_HUB_PN4: EL5610.4 U4601.15
USB_HUB_PP1: EL5609.1 U4601.4
USB_HUB_PP2: EL5321.4 RN5404.2(A) U4601.7
USB_HUB_PP3: NGFFE1.3 U4601.13
USB_HUB_PP4: EL5610.1 U4601.16
USB_OC#_0: C2908.1 C15192.1 CPU1.P14 R2904.2 R2910.1 R6559.1 U2901.6 U2903.6 U3701.3 U3703.3
USB_OC#_1: C2907.1 C15191.1 CPU1.P16 R2903.2 R2908.1 R6558.1 U3702.3 U3801.3 U6510.6 U6511.6
USB_OTG_ID: CPU1.B48 R6562.1 R9864.1
USB_RCOMP: CPU1.A48 R6561.1
USB_RJ45_PN2: ED2801.6 EL5322.3 U3RJ1.11
USB_RJ45_PN3: ED2801.3 EL5323.3 U3RJ1.2
USB_RJ45_PP2: ED2801.1 EL5322.2 U3RJ1.12
USB_RJ45_PP3: ED2801.4 EL5323.2 U3RJ1.3
USB_VBUSSNS: CPU1.B47 R1601.2 R1602.1 R9867.2
USB_VDDQ_G31_H44: C1108.1 CPU1.H44 R2130.1
USBVCC4: ED2907.5 R3702.2 R9705.2 RN5410.5(B) RN5410.6(B) RN5410.7(B) RN5410.8(B) U2901.7 U2901.8 U3703.1 USB2F1.5 USB3F1.19
USBVCC4_EN: C15183.1 R9830.2 R9831.2 U2901.4 U3703.4
USBVCC23: C2911.1 ED6512.5 R2904.1 R3701.2 R9705.1 TC4603.1 U2903.7 U2903.8 U3701.1 USB2F2.9 USB2F2.10 USB3F1.1
USBVCC23_EN: C2912.1 R9828.2 R9829.2 U2903.4 U3701.4
VCORE_PG: PC4409.1 PR4401.2 PU4401.6 R9761.1
VCORE_VR_HOT: PR9757.2 PU4401.2 R9743.1
VGA_BLUE_P: C5308.1 L5303.1 R2420.1 U6506.10
VGA_DDC_CLK: R2413.1 R2415.2 U6506.4
VGA_DDC_DATA: R2412.1 R2414.2 U6506.6
VGA_DDC_PU: C20.1 D2402.K ED2.5 R2414.1 R2415.1
VGA_GREEN_P: C5307.1 L5302.1 R2419.1 U6506.12
VGA_HSYNC: R9658.2 U6506.8
VGA_RED_P: C5301.1 L5301.1 R2418.1 U6506.15
VGA_VSYNC: R9659.2 U6506.7
VGG_PG: D3404.1 PC4509.1 PR4501.2 PU4501.6
VGG_VCC_SEN: CPU1.AD24 PR4510.1 PR9764.2
VGG_VR_HOT#: PR9742.2 PU4501.2 R9742.1
VGG_VSS_SEN: CPU1.AD22 PC4514.1 PR4511.2 PR9765.1
VNN_VCC_SEN: CPU1.AC27 PR4717.1 PR9766.2
VRD_THERMDA: C2019.1 R2018.1 R2020.1 SIO1.46
VTT_CT_3.3V_NORM: C5414.1 U5401.12
VTT_CT_5VC_NORM: C5412.1 U5401.10
W1_DISABLE_N: NGFFE1.56 R6101.1 R6106.1 SIO1.42
W3_DISABLE: NGFFE1.54 R6102.1 R6107.1 R6110.2
W3_DISABLE_N: R6110.1 SIO1.7
WLAN_CLKREQ_CPU#: NGFFE1.53 Q6546.E R9847.2 R9853.2
WLAN_CLKREQ_CPU#_1D8: CPU1.AK14 Q6546.C R1802.1 R6574.1 R9846.2 R9853.1
WLAN_REQ#_Q_B: Q6546.B R9848.2
XDP_COREPWROK: R9606.2 XDP1.45
XDP_HLT_BOOT: C9606.2 R9608.2 XDP1.47
XDP_PMU_RSTBTN_N: C9604.1 R9613.1 XDP1.48
XDP_PRDY#: CPU1.AD45 XDP1.5
XDP_PREQ#: CPU1.AF41 R9620.2 R9621.1
XDP_PREQ#_C: C9605.2 R9621.2 XDP1.3
XDP_PRESENT_N: R9611.1 R9622.2 XDP1.60
XDP_RSMRST_N: R9604.2 XDP1.39
XDP_RST#_R: R9607.1 XDP1.46
XDP_TCK: CPU1.AF42 R1938.2 XDP1.57
XDP_TDI: CPU1.AD47 R1943.2 XDP1.56
XDP_TDO: CPU1.AF40 R1944.2 XDP1.52
XDP_TMS: CPU1.AD48 R1942.2 XDP1.58
XDP_TRST#: CPU1.AB48 R1940.2 XDP1.54
XTAL19D2M_IN: C1501.1 CPU1.P24 R1530.2 X1501.3
XTAL19D2M_OUT: C1502.1 CPU1.M22 R1530.1 X1501.1

Pads without a net: ATX1 20; ATX2 18; AUDH1 7; AUDIO1 2 12 18 19 20 33 37 39 41 43 44 45 46 48; CMOS1 1; CPU1 A3 A9 A37 A49 A51 A52 AA1 AA3 AA30 AB2 AB3 AB7 AB9 AC1 AC3 AC51 AD2 AD3 AD6 AD13 AD14 AE4 AF3 AF6 AF7 AF9 AF44 AF45 AF48 AF50 AG1 AG3 AH2 AH6 AH7 AH45 AK6 AK9 AK10 AK12 AK13 AT24 AT30 AU24 AU30 B4 B5 B7 B8 B10 B12 B16 B20 B38 B49 B50 B53 C7 C9 C11 C16 C19 C37 C38 C49 C53 D2 D6 D12 D14 D36 D48 D52 E8 E52 E53 F2 F7 F10 F12 F36 G2 G36 G44 H3 H5 H7 H46 H47 J1 J3 J12 J14 J26 J36 K2 K3 K6 K7 K9 K10 K20 K26 K38 K44 K47 K48 L3 L13 L51 L53 M4 M6 M7 M10 M12 M20 M26 M32 M34 M36 M38 M44 M47 M48 M51 M52 N26 N34 N36 P6 P7 P9 P26 P28 P30 P34 P45 P47 P48 P50 P51 P52 R53 T6 T7 T10 T12 T13 T41 T42 T44 T45 T48 T50 V6 V7 V9 V10 V12 V13 V14 V45 V47 V48 V50 V51 V52 W53 Y2 Y3 Y6 Y7 Y12 Y13 Y41 Y47 Y48; D3403 2; DBGH1 5 11 13; DIMM1 77 122 125; DIMM2 77 122 125; DIMM3 77 122 125; ED2303 6; ED2304 6; ED2907 3 4; ED3203 6; ED6520 6; HDMI1 13 14; HDMI2 13 14; LEDH1 9 10 13; NGFFE1 8 9 10 11 12 13 14 15 17 19 20 21 22 23 32 34 36 38 40 42 44 46 48 59 61 62 64 65 66 67 68 70 71 73 76 77; PCIE16 A5 A6 A7 A8 A19 A25 A26 A29 A30 A32 A33 A35 A36 A39 A40 A43 A44 A47 A48 A50 A52 A53 A56 A57 A60 A61 A64 A65 A68 A69 A72 A73 A76 A77 A80 A81 B9 B12 B23 B24 B27 B28 B30 B31 B33 B34 B37 B38 B41 B42 B45 B46 B48 B50 B51 B54 B55 B58 B59 B62 B63 B66 B67 B70 B71 B74 B75 B78 B79 B81 B82; PU4203 5 6 7; PU5102 4; SIO1 1 2 56 58; U6506 17; USB2F1 1; USB2F2 1; USB3F1 20; VGA1 4 11; XDP1 6 22 23 24 55

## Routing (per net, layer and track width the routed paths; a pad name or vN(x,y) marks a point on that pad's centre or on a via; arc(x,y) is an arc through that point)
GND: length 0
CLKIN: length 1.2
  TOP w0.102: R9816.2 115.98,27.05 116.31,26.72

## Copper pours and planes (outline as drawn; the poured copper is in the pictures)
5V_DUAL on L2VCC: 196.56,11.6 196.56,28.2 196,28.75 194.37,30.38 194.37,56.85 193.13,58.09 192.98,58.24 192.98,67.13 189.42,70.69 189.42,125.25 181.78,132.9 181.78,141.5 187.53,147.26 189.66,147.26 189.93,146.99 189.93,146.03 184.62,140.72 184.62,134.36 193.61,125.37 193.61,73.2 194.36,72.45 197.53,72.45 198.18,71.8 198.18,11.89 197.89,11.6
5V_DUAL on L2VCC: 155.88,13.09 153.95,15.02 135.87,15.02 133.43,17.46 95.07,17.46 93.8,18.73 79.45,18.73 75.5,22.68 75.5,35.12 78.15,35.12 78.68,34.59 78.68,32.05 81.85,28.88 81.85,27.48 85.39,23.94 133.65,23.94 138.5,19.09 163.43,19.09 163.73,19.39 165.73,17.39 189.1,17.39 189.52,16.96 189.52,13.52 189.1,13.09 188.67,13.09 188.65,13.12 188.49,13.12 188.47,13.09
5V_DUAL on L2VCC: 12.52,29.91 12.28,30.15 12.28,31.11 13.74,32.58 18.01,32.58 22.71,37.27 24.69,37.27 24.71,37.25 24.87,37.25 24.89,37.27 28.53,37.27 29.57,38.32 36.32,38.32 36.61,38.02 36.61,34.01 36.14,33.54 29.33,33.54 25.7,29.91
5V_S0 on L2VCC: 123.95,3.59 147.73,3.59 148.25,4.11 148.25,7.06 147.25,8.06 141.79,8.06 139.51,10.34 139.51,11.75 150.47,11.75 154.94,7.28 183.82,7.28 189.9,13.36 189.9,16.91 189.93,16.94 189.93,17.1 189.9,17.12 189.9,17.93 189.93,17.96 189.93,18.11 189.9,18.14 189.9,28.47 190.07,28.64 195.58,28.64 196.18,28.04 196.18,11.53 195.96,11.32 193.65,11.32 189.4,7.06 186.44,4.11 184.05,1.71 45.06,1.71 42.58,4.19 42.58,7.57 38.86,11.29 33.45,11.29 29.81,7.65 29.81,5.69 29.26,5.14 9.93,5.14 3.64,11.43 3.64,31.93 12.3,40.58 20.14,40.58 22.71,43.14 24.71,43.14 25.03,42.82 25.03,38.1 24.6,37.67 24.6,37.66 22.55,37.66 17.85,32.96 13.59,32.96 12.01,31.38 10.51,31.38 9.99,30.86 9.99,15.75 17.16,8.58 17.16,8.56 17.27,8.45 17.43,8.45 17.45,8.47 26.22,8.47 27.17,9.42 27.17,11.48 31.52,15.84 43.36,15.84 46.65,12.54 46.65,5.51 47.11,5.04 49.44,5.04 49.44,3.96 49.81,3.59 73.87,3.59 74.42,4.15 79.35,4.15 79.91,3.59 113.54,3.59 114.66,4.71 122.83,4.71
5V_SB on L2VCC: 165.89,17.77 160.21,23.45 160.21,31.8 160.73,32.32 162.35,32.32 172.77,21.91 180.52,21.91 181.06,21.36 181.06,17.77
12V_S0 on L2VCC: 11.21,111.89 11.21,53.59 11.66,53.15 27.26,53.15 30.56,56.45 69.39,56.45 70.83,55.01 70.83,45.21 73.68,42.35 74.6,42.35 75.12,41.83 75.12,22.53 79.3,18.35 82.99,18.35 82.99,18.34 83.5,17.83 83.5,16.18 84.35,15.33 91.97,15.33 93.39,13.91 131.49,13.91 133.65,11.75 139.13,11.75 139.13,10.18 141.36,7.95 141.63,7.68 147.09,7.68 147.87,6.91 147.87,4.27 147.57,3.98 139.38,3.98 139.38,5.11 137.7,6.79 133.41,6.79 133.41,7.95 131.85,9.51 120.35,9.51 118.87,10.99 92.53,10.99 91.26,12.26 71.73,12.26 68.14,15.85 68.14,37.85 60.25,45.73 37.34,45.73 36.5,46.57 27.76,46.57 24.71,43.52 22.55,43.52 19.99,40.96 10.06,40.96 3.62,47.4 3.62,124.38 5.18,125.95 19.66,125.95 22.14,123.47 22.14,117.07 16.81,111.75 15.4,111.75 14.38,112.76 12.09,112.76
19V_ADP on L2VCC: 93.65,18.35 94.92,17.08 133.27,17.08 135.71,14.64 153.79,14.64 155.72,12.71 188.38,12.71 188.38,12.67 188.53,12.52 183.66,7.66 155.1,7.66 150.62,12.13 133.81,12.13 131.65,14.29 93.55,14.29 92.13,15.71 84.51,15.71 83.88,16.33 83.88,17.83 84.41,18.35
19V_ADP on L2VCC: 142.32,32.7 141.29,33.73 141.29,36.4 140.92,36.77 138.13,36.77 137.68,37.21 138.25,37.78 144.96,37.78 146.34,36.4 146.48,36.26 155.15,36.26 157.69,38.8 160.1,38.8 162.5,41.2 162.5,48.44 167.46,53.4 171.27,53.4 175.92,58.05 180.37,58.05 182.44,60.12 182.44,70.28 182.58,70.42 189.15,70.42 192.6,66.98 192.6,58.24 186.87,52.51 176.32,52.51 169.35,45.54 169.35,41.48 169.07,41.2 160.58,32.7
AGND on L2VCC: 20.38,136.45 21.67,135.16 21.67,132.24 20.33,130.9 13.08,130.9 12.8,131.18 9.75,131.18 7.41,128.84 3.51,128.84 2.1,130.25 2.1,167.43 2.87,168.21 29.12,168.28 29.13,168.28 30.37,167.05 30.37,156.98 33.16,154.19 39.21,154.19 42.91,157.9 42.91,159.57 47.17,163.83 57.97,163.83 58.55,163.26 58.55,158.02 56.9,156.37 56.9,153.76 58.69,151.97 58.69,147.58 58.51,147.4 58.51,144.71 58.35,144.55 58.32,144.55 52.88,139.12 41.61,139.13 38.56,142.18 36.02,142.18 35.13,143.07 29.16,143.07 24.96,147.27 24.96,152.22 22.81,154.37 22.18,154.37 21.54,155 16.08,155 15.75,155.33 14.02,155.33 13.4,154.71 13.4,141.4 14.53,140.27 19.23,140.27 20.38,139.11
GND on TOP: 138.81,131.95 138.68,132.08 138.68,133.73 138.81,133.86 140.08,133.86 140.34,133.6 140.34,132.33 139.95,131.95 ; 3 cut-outs
GND on L2VCC: 1,0.76 0.83,0.83 0.76,1 0.76,169 0.83,169.17 1,169.24 199,169.24 199.17,169.17 199.24,169 199.24,1 199.17,0.83 199,0.76 ; 2 cut-outs
GND on L2VCC: 98.98,91.55 98.93,91.54 98.38,91.59 97.71,92.09 97.13,92.57 97.09,92.61 97.08,92.61 97.02,92.61 94.17,92.61 93.31,93.47 93.18,93.47 93.14,93.51 92.71,93.51 91.67,94.55 90.5,94.55 85.56,99.49 85.56,100.33 86.85,101.61 88.03,101.61 93.24,96.41 94.08,96.41 95.03,97.36 98.98,93.41 99.14,93.41 99.18,93.45 104.46,93.45 106.27,91.63 106.27,91.38 106.24,91.34 104.84,91.34 104.33,90.83 99.88,90.83 99.04,91.5 99.01,91.54 98.99,91.54
GND on L2VCC: 181.44,17.77 181.44,21.52 180.67,22.29 172.93,22.29 162.51,32.7 161.75,32.7 161.43,33.02 169.74,41.32 169.74,45.39 176.48,52.13 187.02,52.13 192.79,57.9 193.99,56.69 193.99,30.22 194.78,29.44 194.75,29.42 194.75,29.02 189.91,29.02 189.52,28.63 189.52,18.09 189.2,17.77
GND on L2VCC: 80.83,5.4 80.06,6.16 73.63,6.16 72.9,5.42 47.27,5.42 47.03,5.67 47.03,12.7 43.51,16.22 31.37,16.22 26.78,11.64 26.78,9.58 26.06,8.85 17.43,8.85 10.38,15.9 10.38,27.71 10.49,27.83 10.51,27.83 12.42,25.92 26.08,25.92 27.67,24.33 27.67,20.22 28.52,19.37 30.97,19.37 31.71,20.11 31.71,24.06 26.05,29.72 29.49,33.16 36.3,33.16 37,33.86 37,38.18 36.48,38.7 29.41,38.7 28.37,37.66 25.78,37.66 25.41,38.03 25.41,42.98 25.06,43.33 27.92,46.19 36.34,46.19 37.18,45.35 60.09,45.35 67.75,37.69 67.75,15.69 70.75,12.7 71.57,11.87 91.11,11.87 92.38,10.6 118.72,10.6 120.19,9.13 131.7,9.13 133.03,7.8 133.03,5.79 132.64,5.4 124.89,5.4 123.73,6.57 113.59,6.57 112.42,5.4 ; 4 cut-outs
VCC_CORE on L2VCC: outline of 84 points within 112.28,88.98 132.42,124.4
1D05V_S5 on L2VCC: outline of 91 points within 87.71,84.57 118.96,117.22
1D8V_S5 on L2VCC: 98.28,91.28 98.33,91.29 98.87,91.24 99.67,90.6 99.67,88.43 99.21,88.43 97.99,87.21 96.39,87.21 95.78,86.6 93.93,86.6 93.09,85.76 92.64,85.76 89.45,88.95 89.45,91.19 81.77,98.87 81.69,98.87 80.94,99.62 80.94,101.9 84.89,105.85 87.25,105.85 87.36,105.97 87.36,105.23 87.34,105.21 87.34,105.05 94.76,97.62 93.93,96.79 93.4,96.79 88.19,101.99 86.69,101.99 85.18,100.49 85.18,99.34 90.35,94.17 91.51,94.17 92.55,93.13 93.14,93.13 93.18,93.17 94.04,92.3 96.97,92.3 97.47,91.89 97.47,91.89 97.52,91.85 97.56,91.82 97.57,91.82 98.22,91.33 98.25,91.29 98.27,91.29
1D35V_S3 on L2VCC: outline of 185 points within 108.43,34.86 175.65,103.56
3D3V_S0 on L2VCC: 49.96,3.98 49.82,4.12 49.82,5.04 73.05,5.04 73.79,5.78 79.91,5.78 80.67,5.02 112.58,5.02 113.74,6.18 123.57,6.18 124.74,5.02 132.79,5.02 133.41,5.64 133.41,6.41 137.54,6.41 139,4.95 139,3.98 124.11,3.98 122.99,5.09 114.5,5.09 113.38,3.98 80.06,3.98 79.5,4.53 74.27,4.53 73.71,3.98
3D3V_SB on L2VCC: 28.68,19.75 28.05,20.37 28.05,24.49 26.24,26.3 12.58,26.3 10.81,28.07 10.81,28.1 10.7,28.21 10.67,28.21 10.38,28.5 10.38,30.71 10.67,31 11.9,31 11.9,29.99 12.37,29.53 25.7,29.53 31.33,23.9 31.33,20.27 30.81,19.75
AD_JK_S_R on L2VCC: 194.52,72.83 193.99,73.36 193.99,125.53 185,134.52 185,140.56 190.31,145.87 190.31,148 190.71,148.4 195.6,148.4 195.87,148.13 195.87,145.32 194,143.45 191.08,143.45 187.24,139.6 187.24,134.34 191.03,130.54 196.82,130.54 198.18,129.18 198.18,73.48 197.53,72.83
GFX_CORE on L2VCC: 83.15,63.49 80.89,65.75 80.89,65.81 80.77,65.93 68.06,65.93 66.65,67.34 66.65,72.53 64.59,74.59 64.59,76.62 66.63,78.65 69.54,78.65 69.62,78.65 71,80.01 76.46,80.01 78.76,82.31 84.61,82.31 85.59,83.29 87.92,83.29 90.02,85.38 93.25,85.38 94.08,86.22 95.94,86.22 96.55,86.83 98.15,86.83 99.37,88.05 100.89,88.05 101,88.16 101,88.21 101.33,88.54 101.59,88.54 102.65,89.61 106.92,89.61 107.01,89.52 107.01,88.76 108.65,87.12 109.7,87.12 109.72,87.13 109.99,87.13 110.1,87.18 111.95,89 112.46,89 114.27,87.19 114.27,86.53 113.92,85.94 113.89,85.9 113.89,85.89 113.88,85.88 113.9,85.83 114.02,84.32 114.01,84.28 114.01,84.28 113.22,83.48 112.33,83.48 111.82,82.97 110.29,82.97 108.35,81.03 106.9,81.03 106.4,80.53 106.4,79.95 105.61,79.16 104.96,79.16 102.45,76.64 101.63,76.64 97.78,72.79 97.78,71.59 89.67,63.49
PWR_1D24V_FB on TOP: 97.51,129.04 97.13,129.43 97.13,129.44 96.44,130.12 96.44,131.32 95.43,132.33 95.43,132.44 95.83,132.84 95.89,132.84 97.49,131.24 97.94,131.24 98.98,130.2 98.98,129.92 98.11,129.04 ; 5 cut-outs
PWR_VCC0_SW on L2VCC: 109.68,120.08 104.93,124.83 104.93,127.94 108.57,127.94 108.88,127.63 108.88,126.4 109.31,125.97 110.95,125.97 111.68,126.71 111.68,127.19 111.86,127.37 112.97,127.37 113.63,128.03 113.63,131.24 114.21,131.83 119.14,131.83 119.38,131.58 119.38,125.9 117.32,123.83 116.5,123.02 113.71,123.02 112.46,121.77 112.46,120.35 112.19,120.08
PWR_VCC0_VIN on L2VCC: 111.7,134.44 110.99,133.73 110.93,133.59 110.93,128.64 110.68,128.38 108.63,128.38 108.57,128.32 105.09,128.32 105.09,135.06 105.88,135.95 106.76,135.95 106.79,135.94 106.84,135.95 106.89,135.95 106.91,135.98 106.94,135.99 106.96,136.03 107,136.07 107,136.1 107.34,136.79 107.38,136.83 107.38,136.86 107.39,136.89 107.38,136.94 107.38,139.62 108.54,140.78 119.3,140.78 119.95,140.13 119.95,137.37 119.43,136.84 113.59,136.84 113.09,136.35 113.09,134.95 112.7,134.56 111.96,134.56

Small or netless copper shapes (teardrops, artwork), in the pictures only: 4 on TOP, 4 on BOTTOM

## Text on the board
Ref Des/Silkscreen Bottom: B | OSC1:48MHZ | C | A | F2301:1.1A/6V | F2402:1.1A/6V
Ref Des/Silkscreen Top: X3501:12MHZ | X3502:32.768KHZ | X1501:19.2MHZ | X2101:25MHZ | G | F | E | J | I | D | A | K | H | DIBSWL-aBrian 4L MB | 14074-1 | 348.02202.0011 | MADE IN TAIWAN
User.30: AGND | 3D3V_SB | GND | 5V_DUAL | 3D3V_S0 | 1D8V_S5 | 1D05V_S5 | PWR_VCC0_VIN | PWR_VCC0_SW | GFX_CORE | VCC_CORE | 12V_S0 | 19V_ADP | 5V_SB | 1D35V_S3 | 5V_S0 | AD_JK_S_R
